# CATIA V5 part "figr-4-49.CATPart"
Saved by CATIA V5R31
Part number: Part1
Bounding box of the stored display mesh (mm): x -89.975 to 89.975, y -89.975 to 89.975, z 0 to 190
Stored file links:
  D:\PROJECTS\Project 2021\US EDITION\CATIA V5 6R 2021\Resources\Part Files\c04_catia_v5_6r2020_prt\figr-4-49.CATPart
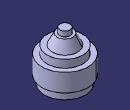
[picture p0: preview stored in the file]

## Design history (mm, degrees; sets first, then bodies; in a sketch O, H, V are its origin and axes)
Set1
  Line1 "Y Axis": stored without definition
  Line2 "Y Axis": stored without definition
  Line3 "X Axis": stored without definition
  Line4 "Z Axis": stored without definition
Body1 (main body)
  Sketch1 on yz-plane, origin (0, 0, 0), H (0, 1, 0), V (0, 0, 1)
    line L1 (0, 0) -> (80, 0)
    line L2 (80, 0) -> (80, 30)
    line L3 (80, 30) -> (90, 30)
    line L4 (90, 30) -> (90, 100)
    line L5 (90, 100) -> (70, 100)
    line L6 (70, 100) -> (70, 130)
    line L7 (70, 130) -> (50, 130)
    line L8 (50, 130) -> (30, 170)
    line L9 (30, 170) -> (20, 170)
    line L10 (20, 170) -> (20, 190)
    line L11 (20, 190) -> (0, 190)
    point P11 (0, 190)
    line L12 (0, 190) -> (0, 0)
    axis line L13 (0, -40) -> (0, 230)
    point P12 (0, -40)
    point P13 (0, 230)
    horizontal: L1 H, L3 H, L5 H, L7 H, L9 H, L11 H
    vertical: L2 V, L4 V, L6 V, L10 V, L12 V, L13 V
    coincidence: P11 V, P12 V, P13 L8
  Shaft1: profile Sketch1, axis Sketch1.L13, angle 360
